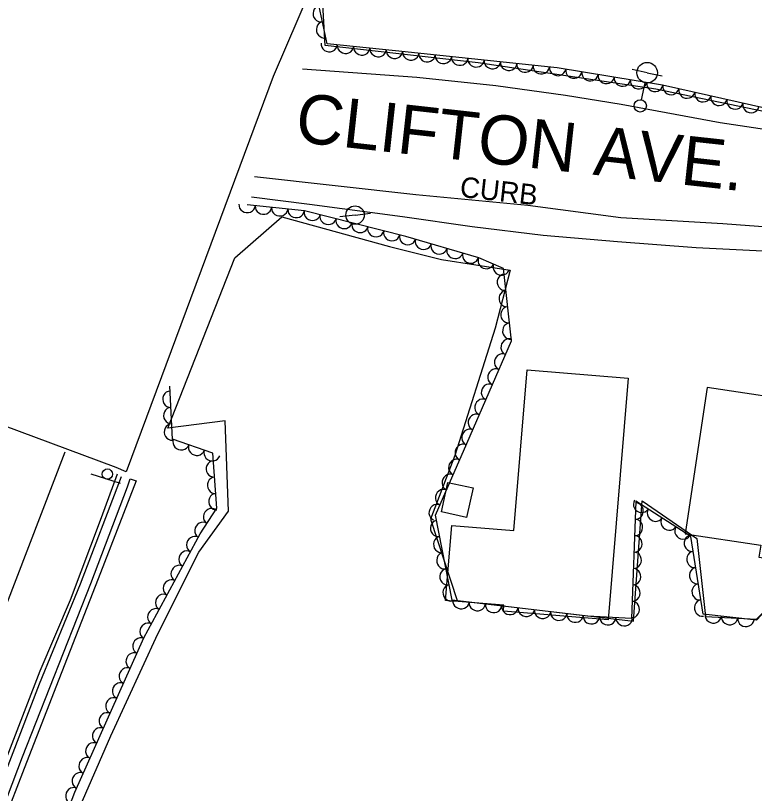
# Model space of a CAD drawing. Extents: x 1722896 to 1754269, y 648279 to 666297.
# Drawn here: x 1725986.7 to 1726166.8, y 665460.1 to 665649.8 of the extents above; entities that cross this region are included whole.
import ezdxf

# ---------------------------------------------------------------- set-up
doc = ezdxf.new("R2010")
doc.units = 0
for name, color, linetype in [('DESIGN - CENTERLINE - Proposed', 7, 'Continuous'), ('DESIGN - CENTERLINE - Proposed Text', 7, 'Continuous'), ('DESIGN - PUBLIC HEARING - Shapes', 7, 'Continuous'), ('DESIGN - SCRATCH - User 1', 7, 'Continuous'), ('DESIGN - SHEET - Linework', 7, 'Continuous'), ('SURVEY - CENTERLINE - Preliminary', 7, 'Continuous'), ('SURVEY - CENTERLINE - Preliminary Text', 7, 'Continuous'), ('SURVEY - DTM - Breaklines', 7, 'Continuous'), ('SURVEY - VEGETATION - Features with Text', 7, 'Continuous')]:
    doc.layers.add(name, color=color, linetype=linetype)

msp = doc.modelspace()

# ---------------------------------------------------------------- linework, layer by layer
at = {"layer": 'DESIGN - CENTERLINE - Proposed'}
for points in [[(1726071.21, 665685.6), (1726049.47, 665634.89), (1726034.3, 665594), (1726013.61, 665538.52)], [(1726013.61, 665538.52), (1726011.23, 665539.61), (1725939.79, 665566.14), (1725960.15, 665615.38)]]:
    msp.add_lwpolyline(points, dxfattribs=at)
at = {"layer": 'DESIGN - CENTERLINE - Proposed Text'}
for points in [[(1726136, 665561.39), (1726131.13, 665502.47), (1726105.6, 665504.58), (1726105.72, 665506), (1726091.49, 665507.17), (1726093, 665525.46), (1726108.12, 665524.21), (1726111.36, 665563.43)], [(1726155.29, 665559.06), (1726149.92, 665523.44), (1726168.33, 665520.66), (1726167.88, 665517.69), (1726175.38, 665516.56), (1726181.2, 665555.15)], [(1726098.2, 665534.6), (1726096.63, 665527.43), (1726090.47, 665528.77), (1726092.04, 665535.95)]]:
    msp.add_lwpolyline(points, close=True, dxfattribs=at)
at = {"layer": 'DESIGN - PUBLIC HEARING - Shapes'}
msp.add_line((1726012.25, 665535.65), (1726005.13, 665537.99), dxfattribs=at)
msp.add_circle((1726009.05, 665537.99), 1.25, dxfattribs=at)
at = {"layer": 'DESIGN - SCRATCH - User 1'}
for points in [[(1726012.44, 665537.33), (1726002.38, 665511.12), (1725992.44, 665486.79), (1725983.29, 665463.08), (1725972.66, 665435.58), (1725960.82, 665405.5), (1725949.79, 665376.77), (1725940.2, 665349.64), (1725931.18, 665322.12), (1725923.35, 665298.61), (1725914.47, 665268.65), (1725906.02, 665238.03), (1725898, 665207.41), (1725890.33, 665178.21), (1725881.8, 665143.8), (1725874.04, 665109.07), (1725866.96, 665078.91), (1725860.32, 665046.15), (1725854.02, 665013.34), (1725848.65, 664982.48), (1725843.84, 664953.56), (1725838.72, 664919.23), (1725833.98, 664888.57), (1725827.92, 664848.71)], [(1726011.41, 665537.98), (1726007.52, 665527.33), (1725999.96, 665507.26), (1725992.56, 665489.93), (1725983.13, 665465.51), (1725973.27, 665440.31), (1725963.63, 665415.13), (1725954.21, 665391.53), (1725945.23, 665367.2), (1725935.1, 665337.51), (1725925.26, 665307.38), (1725916.28, 665278.41), (1725908.67, 665251.41)], [(1726016.04, 665536.36), (1726006.83, 665512.48), (1725997.19, 665487.88), (1725988.8, 665466.2), (1725978.8, 665440.55), (1725964.81, 665404.67), (1725956.39, 665381.61), (1725951.68, 665366.77), (1725944.19, 665342.94), (1725936.5, 665319.23), (1725933.35, 665307.55), (1725931.65, 665303.51), (1725927.81, 665295.29), (1725921.72, 665274.11), (1725914.74, 665249.23), (1725907.9, 665224.3), (1725899.94, 665192.87), (1725891.39, 665158.24)], [(1725892.22, 665167.55), (1725898.74, 665192.52), (1725906.41, 665223.6), (1725913.51, 665249.12), (1725920.32, 665273.33), (1725927.21, 665296.78), (1725931.97, 665307.23), (1725937.31, 665325.21), (1725945.45, 665351.15), (1725951.71, 665370.69), (1725959.25, 665393.47), (1725963.59, 665405.07), (1725972.05, 665426.76), (1725979.83, 665446.68), (1725988.33, 665469.08), (1726004.98, 665511.34), (1726013.98, 665534.84), (1726014.59, 665536.82), (1726016.04, 665536.36)]]:
    msp.add_lwpolyline(points, dxfattribs=at)
at = {"layer": 'SURVEY - CENTERLINE - Preliminary'}
for points in [[(1726359.05, 665787.09), (1726352.23, 665759.64), (1726339.64, 665700.49), (1726320.06, 665700.79), (1726305.9, 665704.1), (1726308.01, 665652.93), (1726316.41, 665631.07), (1726312.54, 665610.19), (1726293.2, 665607.09), (1726268.67, 665609.77), (1726182.74, 665623.49), (1726142.78, 665631.84), (1726099.44, 665638.25), (1726062.18, 665642.48), (1726061.53, 665654.04), (1726069.19, 665667.75), (1726075.68, 665679.13), (1726091.59, 665717.69), (1726359.05, 665787.09)], [(1725996.34, 665443.05), (1726009.87, 665474.21), (1726021.36, 665499.08), (1726031.34, 665518.95), (1726038.58, 665528.92), (1726037.78, 665550.99), (1726023.76, 665549.18), (1726040.09, 665590.67), (1726051.61, 665600.7), (1726077.8, 665593.42), (1726090.47, 665590.25), (1726107.25, 665587.71), (1726103.58, 665573.51), (1726093.79, 665542.48), (1726087.86, 665526.96), (1726094.36, 665507.17), (1726137.29, 665502.1), (1726139.43, 665531.44), (1726152.74, 665522.3), (1726154.9, 665503.29), (1726167.29, 665502.64), (1726181.05, 665516.33), (1726201.82, 665499.4), (1726229.14, 665487.41)]]:
    msp.add_lwpolyline(points, dxfattribs=at)
at = {"layer": 'SURVEY - CENTERLINE - Preliminary Text'}
for points in [[(1726056.62, 665636.77), (1726084.47, 665634.73), (1726103.71, 665632.72), (1726120.77, 665630.38), (1726134.27, 665628.13)], [(1726134.27, 665628.13), (1726158.4, 665623.68), (1726182.8, 665620.05), (1726219.61, 665617.27)], [(1726179.69, 665597.45), (1726159.05, 665598.95), (1726134.24, 665600.43), (1726111.57, 665603.43), (1726084.23, 665606.05), (1726044.94, 665610.4)], [(1726178.62, 665591.86), (1726152.56, 665593.16), (1726133.44, 665594.63), (1726115.32, 665596.14), (1726097.97, 665598.26), (1726080.99, 665600.69), (1726058.31, 665603.66), (1726044.16, 665605.52)], [(1725998.71, 665543.36), (1725984.04, 665505.2), (1725970.9, 665468.78), (1725955.15, 665424.53), (1725940.93, 665383.54), (1725926.92, 665341.85), (1725912.88, 665298.87), (1725899.51, 665252.94), (1725886.48, 665204.23), (1725876.06, 665162.07), (1725869.79, 665135.83), (1725859.22, 665088.82), (1725849.04, 665041.56), (1725843.45, 665012.1), (1725837.66, 664979.41), (1725830.68, 664936.62), (1725824.54, 664897.87), (1725817.95, 664853.26)]]:
    msp.add_lwpolyline(points, dxfattribs=at)
at = {"layer": 'SURVEY - DTM - Breaklines'}
for p, q in [((1726140.63, 665635.82), (1726136.96, 665636.58)), ((1726140.63, 665635.82), (1726144.31, 665635.07)), ((1726139.27, 665629.21), (1726140.13, 665633.37)), ((1726069.44, 665601.12), (1726065.71, 665600.67)), ((1726069.44, 665601.12), (1726073.16, 665601.57))]:
    msp.add_line(p, q, dxfattribs=at)
for centre, radius in [((1726140.63, 665635.82), 2.5), ((1726138.97, 665627.74), 1.5), ((1726069.44, 665601.12), 2.25)]:
    msp.add_circle(centre, radius, dxfattribs=at)
at = {"layer": 'SURVEY - VEGETATION - Features with Text'}
for points in [[(1726306.1, 665608.5), (1726291.16, 665607.01), (1726270.6, 665610.09), (1726245.27, 665614.76), (1726229.14, 665617.57), (1726199.79, 665622.6), (1726170.09, 665626.99), (1726144.4, 665632.81), (1726118.72, 665636.99), (1726079.25, 665641.16), (1726062.62, 665642.84), (1726059.98, 665655.44), (1726074.93, 665685.51)], [(1726203.07, 665499.67), (1726200.57, 665500.85), (1726180.29, 665516.38), (1726167.33, 665502.41), (1726154.31, 665503.8), (1726151.29, 665522.77), (1726137.91, 665531.39), (1726136.8, 665502.76), (1726126.12, 665503.37), (1726093.07, 665507.28), (1726089.06, 665527.98), (1726096.66, 665545.44), (1726107.54, 665570.49), (1726105.6, 665588.13), (1726099.64, 665590.67), (1726081.78, 665595.89), (1726057.13, 665602.14), (1726043.11, 665603.59)], [(1725941.28, 665263.39), (1725953.3, 665311.26), (1725964.41, 665349.48), (1725977.61, 665385.1), (1725988.4, 665412.67), (1725994.19, 665429.41), (1725993.54, 665440.64), (1726001.1, 665460.44), (1726017.97, 665498.03), (1726031.7, 665523.45), (1726035.73, 665529.71), (1726034.74, 665543.04), (1726024.89, 665546.49), (1726024.28, 665559.4)]]:
    msp.add_lwpolyline(points, dxfattribs=at)
for centre, major_axis in [((1726061.08, 665650.18), (-0.41, 1.96)), ((1726061.9, 665646.27), (-0.41, 1.96)), ((1726063.12, 665642.79), (-1.99, 0.2)), ((1726067.09, 665642.39), (-1.99, 0.2)), ((1726071.07, 665641.99), (-1.99, 0.2)), ((1726075.05, 665641.58), (-1.99, 0.2)), ((1726079.03, 665641.18), (-1.99, 0.2)), ((1726083.01, 665640.76), (-1.99, 0.21)), ((1726086.99, 665640.34), (-1.99, 0.21)), ((1726090.97, 665639.92), (-1.99, 0.21)), ((1726094.95, 665639.5), (-1.99, 0.21)), ((1726098.92, 665639.08), (-1.99, 0.21)), ((1726102.9, 665638.66), (-1.99, 0.21)), ((1726106.88, 665638.24), (-1.99, 0.21)), ((1726110.86, 665637.82), (-1.99, 0.21)), ((1726114.84, 665637.4), (-1.99, 0.21)), ((1726118.81, 665636.97), (-1.97, 0.32)), ((1726122.76, 665636.33), (-1.97, 0.32)), ((1726126.71, 665635.69), (-1.97, 0.32)), ((1726130.66, 665635.05), (-1.97, 0.32)), ((1726134.6, 665634.4), (-1.97, 0.32)), ((1726138.55, 665633.76), (-1.97, 0.32)), ((1726142.5, 665633.12), (-1.97, 0.32)), ((1726146.42, 665632.35), (-1.95, 0.44)), ((1726150.33, 665631.47), (-1.95, 0.44)), ((1726154.23, 665630.58), (-1.95, 0.44)), ((1726158.13, 665629.7), (-1.95, 0.44)), ((1726162.03, 665628.82), (-1.95, 0.44)), ((1726165.93, 665627.93), (-1.95, 0.44)), ((1726043.12, 665603.59), (-1.99, 0.21)), ((1726047.1, 665603.18), (-1.99, 0.21)), ((1726051.08, 665602.77), (-1.99, 0.21)), ((1726055.06, 665602.36), (-1.99, 0.21)), ((1726058.99, 665601.67), (-1.94, 0.49)), ((1726062.86, 665600.69), (-1.94, 0.49)), ((1726066.74, 665599.7), (-1.94, 0.49)), ((1726070.62, 665598.72), (-1.94, 0.49)), ((1726074.49, 665597.73), (-1.94, 0.49)), ((1726078.37, 665596.75), (-1.94, 0.49)), ((1726082.24, 665595.75), (-1.92, 0.56)), ((1726086.08, 665594.63), (-1.92, 0.56)), ((1726089.92, 665593.51), (-1.92, 0.56)), ((1726093.76, 665592.39), (-1.92, 0.56)), ((1726097.6, 665591.27), (-1.92, 0.56)), ((1726101.37, 665589.93), (-1.84, 0.78)), ((1726105.05, 665588.37), (-1.84, 0.78)), ((1726105.97, 665584.75), (-0.22, 1.99)), ((1726106.41, 665580.77), (-0.22, 1.99)), ((1726106.84, 665576.8), (-0.22, 1.99)), ((1726107.28, 665572.82), (-0.22, 1.99)), ((1726106.88, 665568.97), (0.8, 1.83)), ((1726105.28, 665565.3), (0.8, 1.83)), ((1726103.69, 665561.64), (0.8, 1.83)), ((1726102.1, 665557.97), (0.8, 1.83)), ((1726024.43, 665556.23), (-0.09, 2)), ((1726100.5, 665554.3), (0.8, 1.83)), ((1726024.62, 665552.24), (-0.09, 2)), ((1726098.91, 665550.63), (0.8, 1.83)), ((1726024.81, 665548.24), (-0.09, 2)), ((1726097.32, 665546.96), (0.8, 1.83)), ((1726027.01, 665545.74), (-1.89, 0.66)), ((1726030.79, 665544.42), (-1.89, 0.66)), ((1726095.72, 665543.29), (0.8, 1.83)), ((1726034.56, 665543.1), (-1.89, 0.66)), ((1726035.02, 665539.23), (-0.15, 1.99)), ((1726094.13, 665539.62), (0.8, 1.83)), ((1726035.32, 665535.24), (-0.15, 1.99)), ((1726092.53, 665535.96), (0.8, 1.83)), ((1726090.93, 665532.29), (0.8, 1.83)), ((1726035.62, 665531.25), (-0.15, 1.99)), ((1726139.24, 665530.54), (-1.68, 1.08)), ((1726034.4, 665527.65), (1.08, 1.68)), ((1726089.34, 665528.62), (0.8, 1.83)), ((1726137.82, 665528.97), (-0.08, -2)), ((1726142.6, 665528.37), (-1.68, 1.08)), ((1726032.24, 665524.29), (1.08, 1.68)), ((1726089.68, 665524.74), (-0.38, 1.96)), ((1726137.66, 665524.97), (-0.08, -2)), ((1726145.97, 665526.2), (-1.68, 1.08)), ((1726149.33, 665524.04), (-1.68, 1.08)), ((1726030.27, 665520.81), (0.95, 1.76)), ((1726090.44, 665520.81), (-0.38, 1.96)), ((1726137.51, 665520.98), (-0.08, -2)), ((1726151.55, 665521.13), (-0.31, 1.98)), ((1726028.37, 665517.29), (0.95, 1.76)), ((1726091.21, 665516.88), (-0.38, 1.96)), ((1726137.35, 665516.98), (-0.08, -2)), ((1726152.18, 665517.18), (-0.31, 1.98)), ((1726026.47, 665513.77), (0.95, 1.76)), ((1726091.97, 665512.96), (-0.38, 1.96)), ((1726137.2, 665512.98), (-0.08, -2)), ((1726152.81, 665513.23), (-0.31, 1.98)), ((1726024.57, 665510.25), (0.95, 1.76)), ((1726092.73, 665509.03), (-0.38, 1.96)), ((1726137.04, 665508.99), (-0.08, -2)), ((1726153.44, 665509.28), (-0.31, 1.98)), ((1726022.67, 665506.73), (0.95, 1.76)), ((1726095.27, 665507.02), (-1.99, 0.23)), ((1726099.24, 665506.55), (-1.99, 0.23)), ((1726136.89, 665504.99), (-0.08, -2)), ((1726154.06, 665505.33), (-0.31, 1.98)), ((1726020.77, 665503.21), (0.95, 1.76)), ((1726103.21, 665506.08), (-1.99, 0.23)), ((1726107.18, 665505.61), (-1.99, 0.23)), ((1726111.16, 665505.14), (-1.99, 0.23)), ((1726115.13, 665504.67), (-1.99, 0.23)), ((1726119.1, 665504.2), (-1.99, 0.23)), ((1726123.07, 665503.73), (-1.99, 0.23)), ((1726127.05, 665503.32), (-2, 0.12)), ((1726131.04, 665503.09), (-2, 0.12)), ((1726156.75, 665503.54), (-1.99, 0.21)), ((1726160.73, 665503.12), (-1.99, 0.21)), ((1726018.87, 665499.69), (0.95, 1.76)), ((1726135.04, 665502.86), (-2, 0.12)), ((1726164.7, 665502.69), (-1.99, 0.21)), ((1726017.11, 665496.1), (0.82, 1.82)), ((1726015.47, 665492.45), (0.82, 1.82)), ((1726013.83, 665488.8), (0.82, 1.82)), ((1726012.19, 665485.15), (0.82, 1.82)), ((1726010.56, 665481.5), (0.82, 1.82)), ((1726008.92, 665477.85), (0.82, 1.82)), ((1726007.28, 665474.2), (0.82, 1.82)), ((1726005.64, 665470.55), (0.82, 1.82)), ((1726004, 665466.91), (0.82, 1.82)), ((1726002.37, 665463.26), (0.82, 1.82)), ((1726000.78, 665459.59), (0.71, 1.87))]:
    msp.add_ellipse(centre, major_axis=major_axis, ratio=0.940188, start_param=0, end_param=3.141593, dxfattribs=at)

# ---------------------------------------------------------------- texts
at = {"layer": 'DESIGN - SCRATCH - User 1'}
msp.add_text('CURB', height=5, rotation=353.7177, dxfattribs=at).set_placement((1726094.82, 665605.56))
at = {"layer": 'DESIGN - SHEET - Linework'}
msp.add_text('CLIFTON AVE.', height=12, rotation=353.6814, dxfattribs=at).set_placement((1726054.58, 665619.03))

doc.saveas('drawing.dxf')
